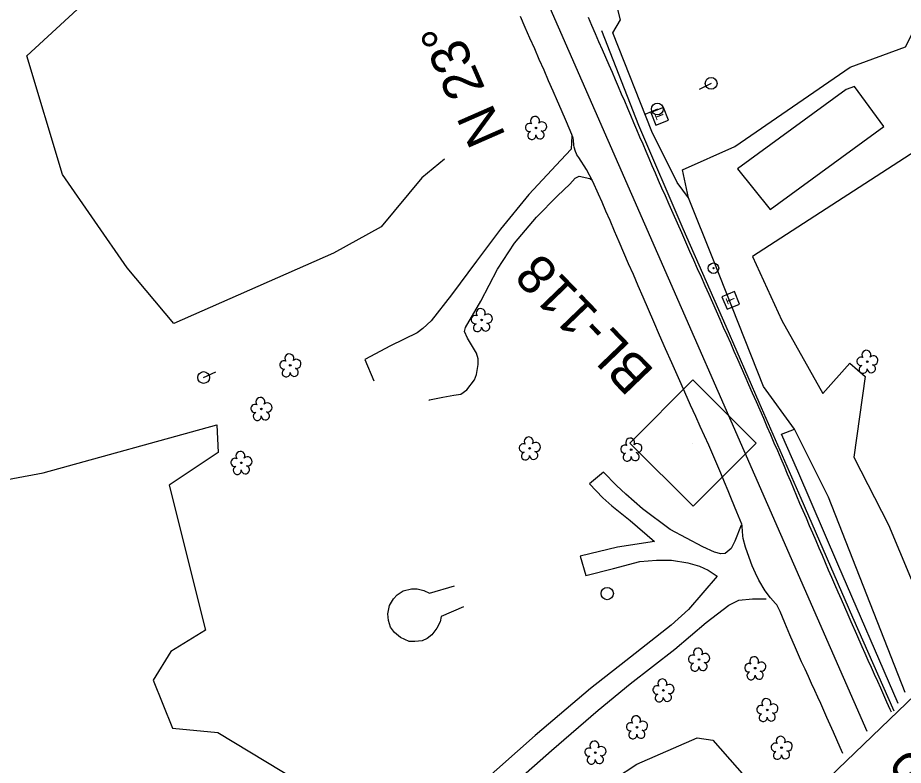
# Model space of a CAD drawing. Extents: x 473158 to 477500, y 500738 to 505114.
# Drawn here: x 475616.1 to 475983.4, y 501699.2 to 502009.2 of the extents above; entities that cross this region are included whole.
import ezdxf

# ---------------------------------------------------------------- set-up
doc = ezdxf.new("R2010")
doc.units = 0
for name, color, linetype in [('CTL Secondary Horizontal and Vertical CELL', 7, 'Continuous'), ('CTL Secondary Horizontal and Vertical Text', 7, 'Continuous'), ('Exist Guardrail', 7, 'Continuous'), ('Exist Horizontal Alignment', 7, 'Continuous'), ('Exist Horizontal Alignment Direction Label', 7, 'Continuous'), ('Exist Other Culture Area Outline', 7, 'Continuous'), ('Exist Other Culture Well CELL', 7, 'Continuous'), ('Exist Roads EOP', 7, 'Continuous'), ('Exist Roads EOP Other', 7, 'Continuous'), ('Exist Roads Soil', 7, 'Continuous'), ('Exist Utilities Other Located Object CELL', 7, 'Continuous'), ('Exist Utilities Power Pole CELL', 7, 'Continuous'), ('Exist Utilities Telephone Pedestal CELL', 7, 'Continuous'), ('Exist Vegetation Hedge Row', 7, 'Continuous'), ('Exist Vegetation Tree CELL', 7, 'Continuous'), ('Exist Vegetation Woods Line', 7, 'Continuous'), ('Matchline', 7, 'Continuous'), ('Matchline Text', 7, 'Continuous')]:
    doc.layers.add(name, color=color, linetype=linetype)

msp = doc.modelspace()

# ---------------------------------------------------------------- linework, layer by layer
at = {"layer": 'CTL Secondary Horizontal and Vertical CELL'}
msp.add_line((475896.05, 501832.73), (475896.05, 501832.73), dxfattribs=at)
msp.add_lwpolyline([(475869.97, 501832.82), (475896.18, 501859.03), (475922.43, 501832.78), (475896.22, 501806.57)], close=True, dxfattribs=at)
at = {"layer": 'Exist Guardrail'}
msp.add_lwpolyline([(475858.22, 502003.88), (475873.57, 501964.57), (475891.99, 501921.71), (475909.74, 501881.21), (475923.46, 501849.74), (475940.91, 501809.98), (475962.4, 501760.56), (475979.45, 501721.73)], dxfattribs=at)
at = {"layer": 'Exist Horizontal Alignment'}
msp.add_line((475968.43, 501713.19), (475772.63, 502159.72), dxfattribs=at)
at = {"layer": 'Exist Other Culture Area Outline'}
msp.add_lwpolyline([(475800.96, 501764.9), (475791.71, 501760.89), (475791.26, 501758.67), (475789.94, 501756.08), (475787.84, 501753.35), (475785.88, 501751.76), (475783.81, 501750.82), (475780.8, 501750.51), (475778.42, 501750.58), (475774.93, 501752.13), (475772.33, 501754.26), (475770.74, 501756.46), (475769.92, 501759.21), (475769.68, 501762.02), (475770.31, 501765.45), (475771.92, 501768.21), (475773.49, 501769.91), (475775.93, 501771.5), (475779.37, 501772.35), (475781.79, 501772.31), (475784.54, 501771.6), (475786.94, 501770.6), (475797.33, 501773.62)], dxfattribs=at)
at = {"layer": 'Exist Other Culture Well CELL'}
msp.add_circle((475860.62, 501770.39), 2.56, dxfattribs=at)
at = {"layer": 'Exist Roads EOP'}
for points in [[(475958.31, 501704.15), (475957.23, 501706.59), (475955.81, 501709.8), (475954.43, 501712.94), (475953.06, 501716.03), (475951.73, 501719.03), (475950.43, 501721.95), (475949.16, 501724.77), (475947.92, 501727.5), (475946.67, 501730.23), (475945.38, 501733.07), (475944.03, 501736.02), (475942.64, 501739.06), (475941.25, 501742.11), (475939.93, 501745.05), (475938.68, 501747.88), (475936.37, 501753.24), (475934.22, 501758.31), (475932.28, 501762.9), (475930.89, 501765.67), (475930.42, 501766.3), (475928.27, 501768.67), (475926.1, 501771.5), (475923.43, 501776.01), (475922.09, 501778.82), (475920.72, 501781.92), (475918.72, 501787.26), (475917.96, 501789.65), (475917.01, 501793.23), (475916.81, 501794.4), (475916.62, 501798.16), (475916.53, 501798.64), (475916.38, 501799.15), (475914.39, 501804.15), (475912.19, 501809.57), (475910.8, 501812.98), (475909.31, 501816.55), (475907.75, 501820.26), (475906.11, 501824.12), (475904.41, 501828.05), (475902.7, 501831.95), (475900.97, 501835.83), (475899.22, 501839.68), (475897.34, 501843.82), (475895.2, 501848.57), (475892.81, 501853.92), (475890.16, 501859.87), (475887.44, 501866.01), (475884.83, 501871.92), (475882.34, 501877.58), (475879.97, 501883.01), (475877.69, 501888.22), (475875.51, 501893.23), (475873.43, 501898.04), (475871.44, 501902.65), (475869.5, 501907.17), (475867.55, 501911.68), (475865.61, 501916.19), (475863.67, 501920.69), (475861.79, 501925.03), (475860.05, 501929.02), (475858.45, 501932.68), (475856.99, 501935.99), (475854.62, 501941.21), (475852, 501946.26), (475848.8, 501951.18), (475848.06, 501952.31), (475847.8, 501952.79), (475847.46, 501953.63), (475846.9, 501955.49), (475846.75, 501956.34), (475846.58, 501958.45), (475846.43, 501959.19), (475845.91, 501960.74), (475843.72, 501965.98), (475841.51, 501971.16), (475840, 501974.63), (475838.22, 501978.67), (475836.31, 501983.02), (475834.39, 501987.4), (475832.45, 501991.81), (475830.52, 501996.25), (475828.57, 502000.7), (475826.61, 502005.17), (475824.64, 502009.66)], [(475852.65, 502009.42), (475854.11, 502006.04), (475855.58, 502002.68), (475857.05, 501999.34), (475858.51, 501996.05), (475859.91, 501992.83), (475861.27, 501989.68), (475862.59, 501986.62), (475863.89, 501983.6), (475865.17, 501980.6), (475866.45, 501977.61), (475867.72, 501974.65), (475868.99, 501971.7), (475870.25, 501968.74), (475871.52, 501965.77), (475872.78, 501962.8), (475874.04, 501959.84), (475875.31, 501956.87), (475876.57, 501953.9), (475877.84, 501950.92), (475879.12, 501947.93), (475880.43, 501944.89), (475881.78, 501941.81), (475883.15, 501938.68), (475884.59, 501935.42), (475886.14, 501931.9), (475887.8, 501928.15), (475889.56, 501924.16), (475891.35, 501920.11), (475893.09, 501916.2), (475894.77, 501912.42), (475896.39, 501908.79), (475897.98, 501905.22), (475899.56, 501901.66), (475901.15, 501898.1), (475902.73, 501894.55), (475904.29, 501891.04), (475905.81, 501887.6), (475907.31, 501884.22), (475908.76, 501880.92), (475910.21, 501877.63), (475911.67, 501874.31), (475913.15, 501870.94), (475914.64, 501867.54), (475916.14, 501864.11), (475917.67, 501860.64), (475919.21, 501857.14), (475920.77, 501853.61), (475922.33, 501850.08), (475923.86, 501846.58), (475925.37, 501843.12), (475926.86, 501839.7), (475928.33, 501836.31), (475929.77, 501832.96), (475931.19, 501829.65), (475932.59, 501826.38), (475933.96, 501823.16), (475935.3, 501820.02), (475936.59, 501816.94), (475937.85, 501813.94), (475939.11, 501810.95), (475940.39, 501807.93), (475941.71, 501804.87), (475943.05, 501801.78), (475944.41, 501798.67), (475945.75, 501795.56), (475947.08, 501792.46), (475948.4, 501789.37), (475949.71, 501786.29), (475951.01, 501783.25), (475952.3, 501780.23), (475953.58, 501777.25), (475954.88, 501774.25), (475956.21, 501771.18), (475957.57, 501768.05), (475958.97, 501764.85), (475960.34, 501761.72), (475961.63, 501758.79), (475963.95, 501753.54), (475966.23, 501748.43), (475967.46, 501745.68), (475968.76, 501742.79), (475970.08, 501739.85), (475971.38, 501736.95), (475972.65, 501734.1), (475973.9, 501731.28), (475975.16, 501728.43), (475976.48, 501725.49), (475977.84, 501722.44), (475978.31, 501721.39)]]:
    msp.add_lwpolyline(points, dxfattribs=at)
at = {"layer": 'Exist Roads EOP Other'}
for points in [[(475845.94, 501960.13), (475845.7, 501954.67)], [(475845.7, 501954.67), (475841.36, 501950.08), (475828.08, 501935.83), (475816.39, 501921.46), (475806.38, 501908.19), (475795.97, 501894.21), (475787.55, 501883.44), (475784.14, 501880.31), (475781.76, 501878.44), (475770.76, 501873.11), (475760.03, 501867.38), (475763.82, 501858.64)], [(475786.67, 501850.5), (475786.85, 501850.7), (475792.42, 501851.89), (475797.01, 501852.6), (475799.9, 501853.12), (475802.41, 501854.84), (475805.51, 501858.97), (475806.39, 501861.19), (475807.04, 501865.43), (475807.07, 501867.78), (475806.4, 501870.14), (475802.67, 501876.27), (475801.48, 501879.05), (475801.89, 501880.76), (475808.13, 501891.57), (475815.09, 501904.96), (475822.14, 501915.7), (475831.31, 501926.46), (475840.05, 501935.36), (475845.1, 501940.15), (475847.36, 501942.59), (475848.93, 501943.43), (475853.45, 501942.53)], [(475853.45, 501942.53), (475854.51, 501941.74)]]:
    msp.add_lwpolyline(points, dxfattribs=at)
at = {"layer": 'Exist Roads Soil'}
for points in [[(475916.14, 501798.72), (475913.47, 501792.18), (475911.99, 501789.1), (475909.56, 501787.01), (475907.75, 501786.9), (475905.09, 501787.52), (475900.21, 501789.72), (475886.77, 501796.92), (475875.22, 501805.47), (475868.31, 501811.55), (475864.44, 501815.22), (475859.03, 501820.71), (475853.22, 501815.89), (475858.8, 501810.12), (475862.5, 501806.82), (475870.07, 501800.63), (475880.19, 501791.92), (475864.89, 501789.58), (475849.36, 501785.86), (475851.72, 501777.86), (475863.23, 501780.79), (475874.14, 501783.65), (475880.98, 501784.18), (475887.31, 501784.26), (475893.98, 501783.13), (475898.87, 501781.77), (475902.45, 501780.14), (475906.15, 501777.61), (475894.38, 501763.85), (475887.11, 501757.23), (475868.32, 501742.46), (475853.66, 501731.01), (475830.78, 501711.61), (475807.52, 501690.93)], [(475849.31, 501597.94), (475838.76, 501611.62), (475827.36, 501626.14), (475817.57, 501638.52), (475806.28, 501653.8), (475801.13, 501662.09), (475799.04, 501666.86), (475798.74, 501669.55), (475799.27, 501671.07), (475801.55, 501673.54), (475811.52, 501682.32), (475822.32, 501691.88), (475837.47, 501705.27), (475856.84, 501721.99), (475870.17, 501733), (475888.6, 501747.32), (475901.67, 501758.36), (475911.09, 501765.57), (475915.17, 501767.66), (475920.89, 501768.24), (475926.56, 501768.26)]]:
    msp.add_lwpolyline(points, dxfattribs=at)
at = {"layer": 'Exist Utilities Other Located Object CELL'}
for radius in [2.18, 0.24]:
    msp.add_circle((475904.65, 501905.3), radius, dxfattribs=at)
at = {"layer": 'Exist Utilities Power Pole CELL'}
for p, q in [((475903.7, 501981.94), (475898.69, 501979.4)), ((475903.7, 501981.94), (475903.7, 501981.94)), ((475881.4, 501971.31), (475876.26, 501969.03)), ((475881.4, 501971.31), (475881.4, 501971.31)), ((475693.22, 501859.97), (475698.34, 501862.31)), ((475693.22, 501859.97), (475693.22, 501859.97))]:
    msp.add_line(p, q, dxfattribs=at)
for centre in [(475903.7, 501981.94), (475881.4, 501971.31), (475693.22, 501859.97)]:
    msp.add_circle(centre, 2.45, dxfattribs=at)
at = {"layer": 'Exist Utilities Telephone Pedestal CELL'}
for p, q in [((475882.36, 501968.23), (475882.36, 501968.23)), ((475911.86, 501891.89), (475911.86, 501891.89))]:
    msp.add_line(p, q, dxfattribs=at)
for points in [[(475885.98, 501966.72), (475883.94, 501971.93), (475878.73, 501969.89), (475880.77, 501964.68), (475885.98, 501966.72)], [(475915.52, 501890.46), (475913.38, 501895.63), (475908.21, 501893.49), (475910.35, 501888.32), (475915.52, 501890.46)]]:
    msp.add_lwpolyline(points, dxfattribs=at)
at = {"layer": 'Exist Vegetation Hedge Row'}
for points in [[(475894.26, 501934.48), (475889.57, 501940.81), (475879.11, 501961.95), (475862.96, 502002.92), (475866.06, 502008.33), (475860.15, 502031.52), (475854.46, 502050.74), (475842.16, 502086.69), (475826.98, 502124.47)], [(475981.22, 501724.87), (475956.28, 501782.58), (475939.62, 501821.15), (475932.88, 501836.43), (475938.29, 501838.59)], [(475840.13, 501665.63), (475854.3, 501687.47), (475872.85, 501699.59), (475897.94, 501710.57), (475904.37, 501709.63), (475921.52, 501690.15), (475931.11, 501679.81)]]:
    msp.add_lwpolyline(points, dxfattribs=at)
at = {"layer": 'Exist Vegetation Tree CELL'}
for p, q in [((475831.06, 501963.48), (475831.06, 501963.48)), ((475808.52, 501883.84), (475808.52, 501883.84)), ((475729.13, 501865.04), (475729.13, 501865.04)), ((475968.47, 501866.53), (475968.47, 501866.53)), ((475717.17, 501846.97), (475717.17, 501846.97)), ((475828.44, 501830.6), (475828.44, 501830.6)), ((475870.54, 501830.1), (475870.54, 501830.1)), ((475708.86, 501824.6), (475708.86, 501824.6)), ((475898.67, 501743.05), (475898.67, 501743.05)), ((475921.95, 501739.47), (475921.95, 501739.47)), ((475883.88, 501730.27), (475883.88, 501730.27)), ((475926.98, 501722.14), (475926.98, 501722.14)), ((475872.92, 501714.98), (475872.92, 501714.98)), ((475932.91, 501706.5), (475932.91, 501706.5)), ((475855.67, 501704.47), (475855.67, 501704.47))]:
    msp.add_line(p, q, dxfattribs=at)
for centre in [(475831.06, 501963.48), (475808.52, 501883.84), (475729.13, 501865.04), (475968.47, 501866.53), (475717.17, 501846.97), (475828.44, 501830.6), (475870.54, 501830.1), (475708.86, 501824.6), (475898.67, 501743.05), (475921.95, 501739.47), (475883.88, 501730.27), (475926.98, 501722.14), (475872.92, 501714.98), (475932.91, 501706.5), (475855.67, 501704.47)]:
    msp.add_circle(centre, 0.326, dxfattribs=at)
for centre, radius, start, end in [((475830.67, 501966.35), 1.86, 330.1651, 219.7134), ((475828.45, 501963.63), 1.73, 62.6636, 279.3457), ((475833.61, 501964.06), 1.9, 257.1011, 134.1999), ((475829.35, 501960.35), 1.69, 111.5671, 6.231), ((475832.73, 501960.58), 1.7, 181.2822, 74.56), ((475808.13, 501886.71), 1.86, 330.1651, 219.7134), ((475811.07, 501884.42), 1.9, 257.1011, 134.1999), ((475805.91, 501883.99), 1.73, 62.6636, 279.3457), ((475806.82, 501880.71), 1.69, 111.5671, 6.231), ((475810.19, 501880.94), 1.7, 181.2822, 74.56), ((475968.08, 501869.4), 1.86, 330.1651, 219.7134), ((475728.75, 501867.92), 1.86, 330.1651, 219.7134), ((475731.68, 501865.63), 1.9, 257.1011, 134.1999), ((475965.86, 501866.68), 1.73, 62.6636, 279.3457), ((475971.01, 501867.11), 1.9, 257.1011, 134.1999), ((475726.53, 501865.2), 1.73, 62.6636, 279.3457), ((475730.8, 501862.15), 1.7, 181.2822, 74.56), ((475966.76, 501863.41), 1.69, 111.5671, 6.231), ((475970.14, 501863.63), 1.7, 181.2822, 74.56), ((475727.43, 501861.92), 1.69, 111.5671, 6.231), ((475716.78, 501849.84), 1.86, 330.1651, 219.7134), ((475719.71, 501847.56), 1.9, 257.1011, 134.1999), ((475714.56, 501847.12), 1.73, 62.6636, 279.3457), ((475715.46, 501843.85), 1.69, 111.5671, 6.231), ((475718.84, 501844.07), 1.7, 181.2822, 74.56), ((475828.05, 501833.47), 1.86, 330.1651, 219.7134), ((475870.15, 501832.97), 1.86, 330.1651, 219.7134), ((475825.83, 501830.75), 1.73, 62.6636, 279.3457), ((475830.99, 501831.19), 1.9, 257.1011, 134.1999), ((475867.93, 501830.25), 1.73, 62.6636, 279.3457), ((475873.09, 501830.69), 1.9, 257.1011, 134.1999), ((475708.48, 501827.48), 1.86, 330.1651, 219.7134), ((475711.41, 501825.19), 1.9, 257.1011, 134.1999), ((475826.73, 501827.48), 1.69, 111.5671, 6.231), ((475830.11, 501827.7), 1.7, 181.2822, 74.56), ((475868.84, 501826.98), 1.69, 111.5671, 6.231), ((475872.21, 501827.2), 1.7, 181.2822, 74.56), ((475706.26, 501824.76), 1.73, 62.6636, 279.3457), ((475710.53, 501821.7), 1.7, 181.2822, 74.56), ((475707.16, 501821.48), 1.69, 111.5671, 6.231), ((475898.28, 501745.92), 1.86, 330.1651, 219.7134), ((475896.06, 501743.2), 1.73, 62.6636, 279.3457), ((475901.22, 501743.64), 1.9, 257.1011, 134.1999), ((475921.56, 501742.34), 1.86, 330.1651, 219.7134), ((475896.96, 501739.93), 1.69, 111.5671, 6.231), ((475900.34, 501740.15), 1.7, 181.2822, 74.56), ((475919.34, 501739.63), 1.73, 62.6636, 279.3457), ((475924.5, 501740.06), 1.9, 257.1011, 134.1999), ((475920.25, 501736.35), 1.69, 111.5671, 6.231), ((475923.62, 501736.57), 1.7, 181.2822, 74.56), ((475881.28, 501730.43), 1.73, 62.6636, 279.3457), ((475883.5, 501733.15), 1.86, 330.1651, 219.7134), ((475886.43, 501730.86), 1.9, 257.1011, 134.1999), ((475882.18, 501727.15), 1.69, 111.5671, 6.231), ((475885.55, 501727.37), 1.7, 181.2822, 74.56), ((475926.6, 501725.01), 1.86, 330.1651, 219.7134), ((475929.53, 501722.73), 1.9, 257.1011, 134.1999), ((475924.38, 501722.29), 1.73, 62.6636, 279.3457), ((475925.28, 501719.02), 1.69, 111.5671, 6.231), ((475928.65, 501719.24), 1.7, 181.2822, 74.56), ((475870.31, 501715.13), 1.73, 62.6636, 279.3457), ((475872.53, 501717.85), 1.86, 330.1651, 219.7134), ((475875.47, 501715.57), 1.9, 257.1011, 134.1999), ((475871.21, 501711.86), 1.69, 111.5671, 6.231), ((475874.59, 501712.08), 1.7, 181.2822, 74.56), ((475932.53, 501709.37), 1.86, 330.1651, 219.7134), ((475853.07, 501704.62), 1.73, 62.6636, 279.3457), ((475855.29, 501707.34), 1.86, 330.1651, 219.7134), ((475858.22, 501705.05), 1.9, 257.1011, 134.1999), ((475930.31, 501706.65), 1.73, 62.6636, 279.3457), ((475935.46, 501707.09), 1.9, 257.1011, 134.1999), ((475853.97, 501701.34), 1.69, 111.5671, 6.231), ((475857.34, 501701.57), 1.7, 181.2822, 74.56), ((475931.21, 501703.38), 1.69, 111.5671, 6.231), ((475934.59, 501703.6), 1.7, 181.2822, 74.56)]:
    msp.add_arc(centre, radius, start, end, dxfattribs=at)
at = {"layer": 'Exist Vegetation Woods Line'}
for points in [[(475984.22, 501729.43), (475952.41, 501810.41), (475938.29, 501838.59), (475925.48, 501856.19), (475904.69, 501908.62), (475894.26, 501934.48), (475891.89, 501946.09), (475913.49, 501955.7), (475961.43, 501988.61), (475984.27, 501997.05), (475993.03, 502014.2), (476022.92, 502016.87), (476044.62, 502036.72), (476070.75, 502055.07), (476072.92, 502057.47)], [(475793.12, 501950.48), (475783.69, 501942.76), (475766.82, 501922.52), (475747.14, 501911.49), (475680.82, 501882.36), (475661.56, 501905.49), (475634.68, 501944.13), (475619.87, 501993.37), (475640.81, 502012.54)], [(476128.63, 501872.15), (476086.9, 501921.65), (476072.81, 501972.58), (476078.45, 501996.77), (476071.32, 502007.46), (476040.62, 501992.73), (475998.06, 501960.08), (475920.84, 501910.21), (475933.06, 501883.66), (475949.97, 501853.37), (475961.22, 501865.91), (475967.63, 501860.36), (475962.83, 501826.92), (475977.25, 501798.93), (475990.98, 501766.15), (475992.56, 501742.41)], [(475963.19, 501980.68), (475959.76, 501979.46), (475914.65, 501946.5)], [(475975.35, 501964.09), (475975.35, 501964.09), (475963.19, 501980.68)], [(475928.14, 501929.68), (475928.14, 501929.68), (475975.35, 501964.09)], [(475914.65, 501946.5), (475914.65, 501946.5), (475928.14, 501929.68)], [(475599.13, 501815.34), (475626.61, 501820.43), (475698.69, 501840.33), (475699.27, 501828.86), (475678.9, 501815.38), (475693.94, 501755.25), (475679.57, 501746.4), (475672.25, 501734.43), (475680.24, 501714.62), (475699.09, 501712.78), (475732.29, 501692.73)]]:
    msp.add_lwpolyline(points, dxfattribs=at)
at = {"layer": 'Matchline'}
msp.add_line((475766.52, 501515.03), (476126.81, 501861.72), dxfattribs=at)

# ---------------------------------------------------------------- texts
at = {"layer": 'CTL Secondary Horizontal and Vertical Text'}
msp.add_text('BL-118', height=16, rotation=133.8723, dxfattribs=at).set_placement((475880.64, 501862.67))
at = {"layer": 'Exist Horizontal Alignment Direction Label'}
msp.add_text('N 23%%d 40\' 35" W', height=16, rotation=113.6764, dxfattribs=at).set_placement((475818.7, 501960.17))
at = {"layer": 'Exist Utilities Telephone Pedestal CELL'}
for rotation, p in [(111.3852, (475884.36, 501967.8)), (112.4911, (475913.88, 501891.51))]:
    msp.add_text('T', height=3.42, rotation=rotation, dxfattribs=at).set_placement(p)
at = {"layer": 'Matchline Text'}
msp.add_text('MATCHLINE SHEET RW02C-5', height=16, rotation=224.2987, dxfattribs=at).set_placement((476079.51, 501797.32))

doc.saveas('drawing.dxf')
